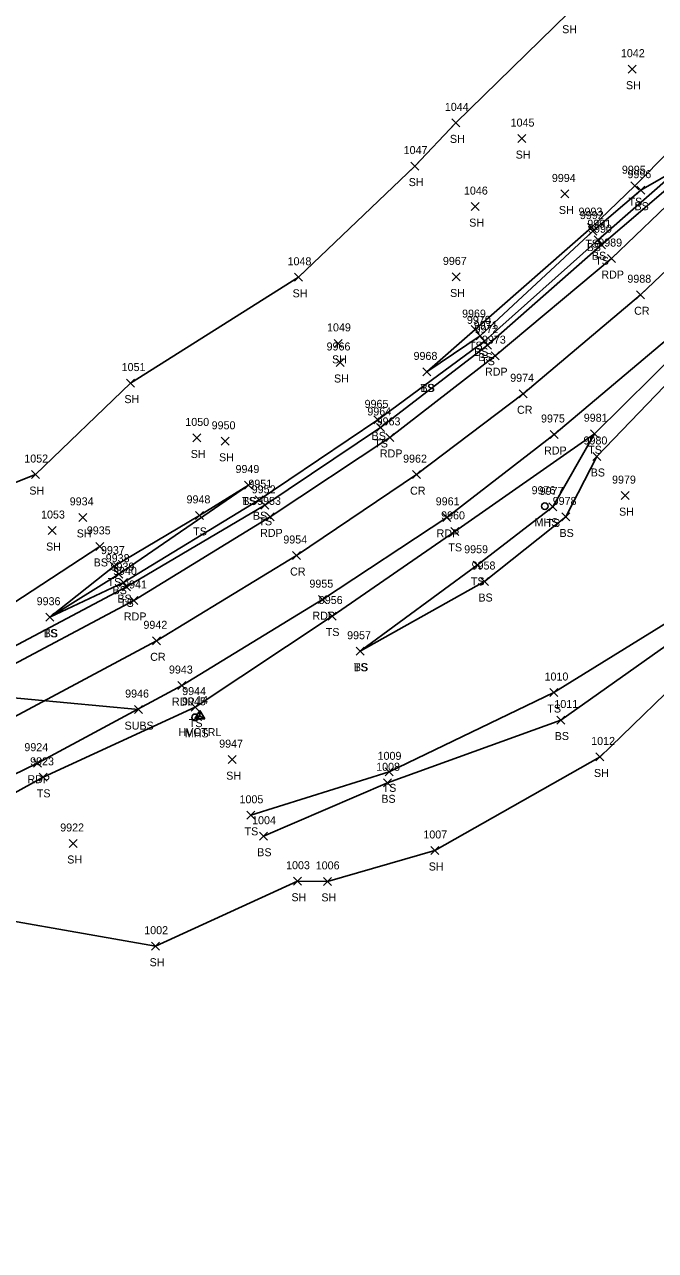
# Model space of a CAD drawing. Extents: x 1651685 to 1653558, y 889533 to 891085.
# Drawn here: x 1652341.8 to 1652499.4, y 889769.1 to 890075.4 of the extents above; entities that cross this region are included whole.
import ezdxf

# ---------------------------------------------------------------- set-up
doc = ezdxf.new("R2010")
doc.units = 0
for name, color, linetype in [('C_A', 7, 'Continuous'), ('C_I', 7, 'Continuous'), ('CPSM', 7, 'Continuous'), ('L_A', 7, 'Continuous'), ('L_I', 7, 'Continuous'), ('L_TIC', 7, 'Continuous'), ('LELB', 7, 'Continuous'), ('LSOGP', 7, 'Continuous'), ('P_A', 7, 'Continuous'), ('P_I', 7, 'Continuous'), ('P_TIC', 7, 'Continuous'), ('PET', 7, 'Continuous'), ('PRC', 7, 'Continuous'), ('U_A', 7, 'Continuous'), ('U_I', 7, 'Continuous'), ('U_TIC', 7, 'Continuous'), ('USA', 7, 'Continuous'), ('USMH', 7, 'Continuous')]:
    doc.layers.add(name, color=color, linetype=linetype)

msp = doc.modelspace()

# ---------------------------------------------------------------- linework, layer by layer
at = {"layer": 'CPSM'}
for p, q in [((1652384.31, 889901.92), (1652385.56, 889904.08)), ((1652386.81, 889901.92), (1652385.56, 889904.08)), ((1652385.56, 889902.64), (1652385.56, 889904.08)), ((1652384.31, 889901.92), (1652385.56, 889902.64)), ((1652384.31, 889901.92), (1652386.81, 889901.92)), ((1652385.56, 889902.64), (1652385.56, 889902.64)), ((1652385.56, 889902.64), (1652386.81, 889901.92))]:
    msp.add_line(p, q, dxfattribs=at)
at = {"layer": 'L_TIC'}
for points in [[(1652492.54, 890063.25), (1652494.54, 890065.25)], [(1652494.54, 890063.25), (1652492.54, 890065.25)], [(1652448.56, 890049.84), (1652450.56, 890051.84)], [(1652450.56, 890049.84), (1652448.56, 890051.84)], [(1652464.99, 890045.91), (1652466.99, 890047.91)], [(1652466.99, 890045.91), (1652464.99, 890047.91)], [(1652438.27, 890039.04), (1652440.27, 890041.04)], [(1652440.27, 890039.04), (1652438.27, 890041.04)], [(1652493.27, 890034.14), (1652495.27, 890036.14)], [(1652495.27, 890034.14), (1652493.27, 890036.14)], [(1652475.78, 890032.08), (1652477.78, 890034.08)], [(1652477.78, 890032.08), (1652475.78, 890034.08)], [(1652494.71, 890033.02), (1652496.71, 890035.02)], [(1652496.71, 890033.02), (1652494.71, 890035.02)], [(1652453.38, 890028.92), (1652455.38, 890030.92)], [(1652455.38, 890028.92), (1652453.38, 890030.92)], [(1652482.45, 890023.67), (1652484.45, 890025.67)], [(1652484.45, 890023.67), (1652482.45, 890025.67)], [(1652482.78, 890022.8), (1652484.78, 890024.8)], [(1652484.78, 890022.8), (1652482.78, 890024.8)], [(1652484.07, 890020.64), (1652486.07, 890022.64)], [(1652486.07, 890020.64), (1652484.07, 890022.64)], [(1652484.92, 890019.39), (1652486.92, 890021.39)], [(1652486.92, 890019.39), (1652484.92, 890021.39)], [(1652409.27, 890011.26), (1652411.27, 890013.26)], [(1652411.27, 890011.26), (1652409.27, 890013.26)], [(1652448.61, 890011.35), (1652450.61, 890013.35)], [(1652450.61, 890011.35), (1652448.61, 890013.35)], [(1652453.4, 889998.19), (1652455.4, 890000.19)], [(1652455.4, 889998.19), (1652453.4, 890000.19)], [(1652419.14, 889994.75), (1652421.14, 889996.75)], [(1652421.14, 889994.75), (1652419.14, 889996.75)], [(1652454.64, 889996.63), (1652456.64, 889998.63)], [(1652456.64, 889996.63), (1652454.64, 889998.63)], [(1652455.7, 889995.32), (1652457.7, 889997.32)], [(1652457.7, 889995.32), (1652455.7, 889997.32)], [(1652456.46, 889994.31), (1652458.46, 889996.31)], [(1652458.46, 889994.31), (1652456.46, 889996.31)], [(1652419.61, 889989.98), (1652421.61, 889991.98)], [(1652421.61, 889989.98), (1652419.61, 889991.98)], [(1652367.26, 889984.83), (1652369.26, 889986.83)], [(1652369.26, 889984.83), (1652367.26, 889986.83)], [(1652441.28, 889987.62), (1652443.28, 889989.62)], [(1652443.28, 889987.62), (1652441.28, 889989.62)], [(1652441.28, 889987.62), (1652443.28, 889989.62)], [(1652443.28, 889987.62), (1652441.28, 889989.62)], [(1652429.05, 889975.64), (1652431.05, 889977.64)], [(1652431.05, 889975.64), (1652429.05, 889977.64)], [(1652429.74, 889973.75), (1652431.74, 889975.75)], [(1652431.74, 889973.75), (1652429.74, 889975.75)], [(1652383.82, 889971.13), (1652385.82, 889973.13)], [(1652385.82, 889971.13), (1652383.82, 889973.13)], [(1652390.89, 889970.29), (1652392.89, 889972.29)], [(1652392.89, 889970.29), (1652390.89, 889972.29)], [(1652483.18, 889972.18), (1652485.18, 889974.18)], [(1652485.18, 889972.18), (1652483.18, 889974.18)], [(1652483.18, 889972.18), (1652485.18, 889974.18)], [(1652485.18, 889972.18), (1652483.18, 889974.18)], [(1652483.78, 889966.5), (1652485.78, 889968.5)], [(1652485.78, 889966.5), (1652483.78, 889968.5)], [(1652343.51, 889961.98), (1652345.51, 889963.98)], [(1652345.51, 889961.98), (1652343.51, 889963.98)], [(1652396.76, 889959.36), (1652398.76, 889961.36)], [(1652398.76, 889959.36), (1652396.76, 889961.36)], [(1652396.76, 889959.36), (1652398.76, 889961.36)], [(1652398.76, 889959.36), (1652396.76, 889961.36)], [(1652399.4, 889955.7), (1652401.4, 889957.7)], [(1652401.4, 889955.7), (1652399.4, 889957.7)], [(1652400.81, 889954.3), (1652402.81, 889956.3)], [(1652402.81, 889954.3), (1652400.81, 889956.3)], [(1652490.82, 889956.72), (1652492.82, 889958.72)], [(1652492.82, 889956.72), (1652490.82, 889958.72)], [(1652355.35, 889951.28), (1652357.35, 889953.28)], [(1652357.35, 889951.28), (1652355.35, 889953.28)], [(1652384.53, 889951.78), (1652386.53, 889953.78)], [(1652386.53, 889951.78), (1652384.53, 889953.78)], [(1652472.73, 889953.89), (1652474.73, 889955.89)], [(1652474.73, 889953.89), (1652472.73, 889955.89)], [(1652475.98, 889951.39), (1652477.98, 889953.39)], [(1652477.98, 889951.39), (1652475.98, 889953.39)], [(1652347.7, 889947.99), (1652349.7, 889949.99)], [(1652349.7, 889947.99), (1652347.7, 889949.99)], [(1652448.26, 889947.79), (1652450.26, 889949.79)], [(1652450.26, 889947.79), (1652448.26, 889949.79)], [(1652359.62, 889944.03), (1652361.62, 889946.03)], [(1652361.62, 889944.03), (1652359.62, 889946.03)], [(1652363.15, 889939.11), (1652365.15, 889941.11)], [(1652365.15, 889939.11), (1652363.15, 889941.11)], [(1652453.88, 889939.32), (1652455.88, 889941.32)], [(1652455.88, 889939.32), (1652453.88, 889941.32)], [(1652364.34, 889937.1), (1652366.34, 889939.1)], [(1652366.34, 889937.1), (1652364.34, 889939.1)], [(1652365.56, 889934.99), (1652367.56, 889936.99)], [(1652367.56, 889934.99), (1652365.56, 889936.99)], [(1652366.25, 889933.93), (1652368.25, 889935.93)], [(1652368.25, 889933.93), (1652366.25, 889935.93)], [(1652455.73, 889935.26), (1652457.73, 889937.26)], [(1652457.73, 889935.26), (1652455.73, 889937.26)], [(1652417.63, 889926.64), (1652419.63, 889928.64)], [(1652419.63, 889926.64), (1652417.63, 889928.64)], [(1652347.15, 889926.34), (1652349.15, 889928.34)], [(1652349.15, 889926.34), (1652347.15, 889928.34)], [(1652347.15, 889926.34), (1652349.15, 889928.34)], [(1652349.15, 889926.34), (1652347.15, 889928.34)], [(1652347.15, 889926.34), (1652349.15, 889928.34)], [(1652349.15, 889926.34), (1652347.15, 889928.34)], [(1652424.64, 889917.85), (1652426.64, 889919.85)], [(1652426.64, 889917.85), (1652424.64, 889919.85)], [(1652424.64, 889917.85), (1652426.64, 889919.85)], [(1652426.64, 889917.85), (1652424.64, 889919.85)], [(1652472.98, 889907.53), (1652474.98, 889909.53)], [(1652474.98, 889907.53), (1652472.98, 889909.53)], [(1652383.44, 889903.89), (1652385.44, 889905.89)], [(1652385.44, 889903.89), (1652383.44, 889905.89)], [(1652474.79, 889900.66), (1652476.79, 889902.66)], [(1652476.79, 889900.66), (1652474.79, 889902.66)], [(1652392.68, 889890.76), (1652394.68, 889892.76)], [(1652394.68, 889890.76), (1652392.68, 889892.76)], [(1652484.54, 889891.44), (1652486.54, 889893.44)], [(1652486.54, 889891.44), (1652484.54, 889893.44)], [(1652431.84, 889887.72), (1652433.84, 889889.72)], [(1652433.84, 889887.72), (1652431.84, 889889.72)], [(1652345.46, 889886.35), (1652347.46, 889888.35)], [(1652347.46, 889886.35), (1652345.46, 889888.35)], [(1652431.48, 889884.98), (1652433.48, 889886.98)], [(1652433.48, 889884.98), (1652431.48, 889886.98)], [(1652397.35, 889876.86), (1652399.35, 889878.86)], [(1652399.35, 889876.86), (1652397.35, 889878.86)], [(1652400.49, 889871.63), (1652402.49, 889873.63)], [(1652402.49, 889871.63), (1652400.49, 889873.63)], [(1652352.97, 889869.82), (1652354.97, 889871.82)], [(1652354.97, 889869.82), (1652352.97, 889871.82)], [(1652443.27, 889868.07), (1652445.27, 889870.07)], [(1652445.27, 889868.07), (1652443.27, 889870.07)], [(1652408.98, 889860.39), (1652410.98, 889862.39)], [(1652410.98, 889860.39), (1652408.98, 889862.39)], [(1652416.45, 889860.35), (1652418.45, 889862.35)], [(1652418.45, 889860.35), (1652416.45, 889862.35)], [(1652373.55, 889844.16), (1652375.55, 889846.16)], [(1652375.55, 889844.16), (1652373.55, 889846.16)]]:
    msp.add_lwpolyline(points, dxfattribs=at)
at = {"layer": 'LELB'}
for points in [[(1652293.22, 889915.66), (1652303.09, 889907.93), (1652317.35, 889908.79), (1652320.69, 889910.3), (1652331.92, 889916.22), (1652367.25, 889934.93), (1652401.81, 889955.3), (1652430.74, 889974.75), (1652457.46, 889995.31), (1652485.92, 890020.39), (1652507.16, 890038.54), (1652516.29, 890046.9), (1652543.45, 890076.69), (1652569.75, 890105.32), (1652598.99, 890142.55), (1652623.84, 890175.33), (1652642.78, 890202.62), (1652649.43, 890213.08), (1652650.34, 890219.8), (1652662.3, 890235.67), (1652673.05, 890250.91), (1652676.63, 890257.99), (1652674.28, 890264.42)], [(1652348.15, 889927.34), (1652366.56, 889935.99), (1652400.4, 889956.7), (1652430.05, 889976.64), (1652456.7, 889996.32), (1652485.07, 890021.64), (1652505.87, 890039.82), (1652515.19, 890048.17), (1652541.97, 890077.83), (1652568.76, 890106.07), (1652597.37, 890144.26), (1652620.77, 890177.54), (1652638.78, 890206.49), (1652647.21, 890219), (1652658.7, 890237.83), (1652668.92, 890254.32), (1652671.69, 890259.27)], [(1652059.96, 889769.15), (1652077.1, 889776.34), (1652118.69, 889793.55), (1652148.83, 889805.14), (1652195.57, 889824.7), (1652235.22, 889839.02), (1652273.17, 889851.71), (1652312.19, 889868.5), (1652346.46, 889887.35), (1652384.44, 889904.89), (1652418.63, 889927.64), (1652449.26, 889948.79), (1652484.18, 889973.18), (1652505.9, 889994.66), (1652536.9, 890025.51), (1652566.28, 890055.69), (1652594.63, 890083.58), (1652622.18, 890122.04), (1652650.06, 890154.47), (1652669.87, 890181.83), (1652676.09, 890189.41), (1652687.77, 890202.23), (1652700.09, 890224.17)], [(1652442.28, 889988.62), (1652454.4, 889999.19), (1652483.45, 890024.67), (1652494.27, 890035.14), (1652511.88, 890052.95), (1652537.3, 890082.09), (1652561.99, 890110.81), (1652590.74, 890149.47), (1652610.85, 890183.15), (1652631.18, 890211.95), (1652637.71, 890221.97)], [(1652425.64, 889918.85), (1652456.73, 889936.26), (1652476.98, 889952.39), (1652484.78, 889967.5), (1652507.93, 889991.53), (1652539.73, 890022.77), (1652568.75, 890053.15), (1652596.44, 890082.38), (1652624.72, 890120.12), (1652650.78, 890153.9), (1652671.99, 890180.33), (1652678.44, 890186.86), (1652688.88, 890200.58)], [(1652442.28, 889988.62), (1652455.64, 889997.63), (1652483.78, 890023.8), (1652495.71, 890034.02), (1652505.87, 890039.82)], [(1652425.64, 889918.85), (1652454.88, 889940.32), (1652473.73, 889954.89), (1652484.18, 889973.18)], [(1652398.35, 889877.86), (1652432.84, 889888.72), (1652473.98, 889908.53), (1652503.63, 889926.84), (1652527.76, 889943.52), (1652552.29, 889965.96)], [(1652348.15, 889927.34), (1652364.15, 889940.11), (1652385.53, 889952.78), (1652397.76, 889960.36)], [(1652348.15, 889927.34), (1652365.34, 889938.1), (1652397.76, 889960.36)], [(1652401.49, 889872.63), (1652432.48, 889885.98), (1652475.79, 889901.66), (1652505.98, 889923.02), (1652542.27, 889949.72)], [(1652298.96, 889913.59), (1652303.02, 889910.85), (1652329.14, 889924.47), (1652360.62, 889945.03)]]:
    msp.add_lwpolyline(points, dxfattribs=at)
at = {"layer": 'LSOGP'}
for points in [[(1652318.58, 889855.03), (1652374.55, 889845.16), (1652409.98, 889861.38), (1652417.45, 889861.35), (1652444.27, 889869.07), (1652485.55, 889892.44), (1652509.97, 889916.1), (1652542.26, 889949.72), (1652552.29, 889965.95), (1652571.67, 889995.46), (1652586.67, 890018.83), (1652616.64, 890057.03), (1652642.24, 890083.82)], [(1652477.61, 890078.23), (1652449.56, 890050.84), (1652439.27, 890040.04), (1652410.27, 890012.27), (1652368.26, 889985.83), (1652344.51, 889962.98), (1652311.88, 889950.06)]]:
    msp.add_lwpolyline(points, dxfattribs=at)
at = {"layer": 'P_TIC'}
for points in [[(1652487.38, 890015.94), (1652489.38, 890017.94)], [(1652489.38, 890015.94), (1652487.38, 890017.94)], [(1652494.64, 890006.9), (1652496.64, 890008.9)], [(1652496.64, 890006.9), (1652494.64, 890008.9)], [(1652458.32, 889991.68), (1652460.32, 889993.68)], [(1652460.32, 889991.68), (1652458.32, 889993.68)], [(1652465.37, 889982.16), (1652467.37, 889984.16)], [(1652467.37, 889982.16), (1652465.37, 889984.16)], [(1652432.06, 889971.26), (1652434.06, 889973.26)], [(1652434.06, 889971.26), (1652432.06, 889973.26)], [(1652473.07, 889971.99), (1652475.07, 889973.99)], [(1652475.07, 889971.99), (1652473.07, 889973.99)], [(1652438.67, 889961.96), (1652440.67, 889963.96)], [(1652440.67, 889961.96), (1652438.67, 889963.96)], [(1652402.15, 889951.41), (1652404.15, 889953.41)], [(1652404.15, 889951.41), (1652402.15, 889953.41)], [(1652446.25, 889951.29), (1652448.25, 889953.29)], [(1652448.25, 889951.29), (1652446.25, 889953.29)], [(1652408.7, 889941.76), (1652410.7, 889943.76)], [(1652410.7, 889941.76), (1652408.7, 889943.76)], [(1652368.12, 889930.53), (1652370.12, 889932.53)], [(1652370.12, 889930.53), (1652368.12, 889932.53)], [(1652415.22, 889930.73), (1652417.22, 889932.73)], [(1652417.22, 889930.73), (1652415.22, 889932.73)], [(1652373.76, 889920.45), (1652375.76, 889922.45)], [(1652375.76, 889920.45), (1652373.76, 889922.45)], [(1652380.13, 889909.27), (1652382.13, 889911.27)], [(1652382.13, 889909.27), (1652380.13, 889911.27)], [(1652344.02, 889889.88), (1652346.02, 889891.88)], [(1652346.02, 889889.88), (1652344.02, 889891.88)]]:
    msp.add_lwpolyline(points, dxfattribs=at)
at = {"layer": 'PET'}
for points in [[(1652310.07, 889873.86), (1652345.02, 889890.88), (1652381.13, 889910.27), (1652416.22, 889931.73), (1652447.25, 889952.29), (1652474.07, 889972.99), (1652503.7, 889997.94), (1652534.46, 890027.79), (1652563.38, 890057.92), (1652590.11, 890087.92), (1652620.33, 890123.88), (1652646.59, 890156.84), (1652667.23, 890184.01), (1652673.84, 890192.76), (1652698.19, 890224.99), (1652707.05, 890238.8), (1652697.14, 890249.86), (1652688.17, 890260.37)], [(1652333.65, 889912.67), (1652369.12, 889931.53), (1652403.15, 889952.41), (1652433.06, 889972.26), (1652459.32, 889992.68), (1652488.38, 890016.94), (1652517.96, 890045.24), (1652545.96, 890074.03), (1652572.08, 890103.38), (1652602.1, 890139.63), (1652627.16, 890172.83), (1652646.68, 890199.42), (1652655.75, 890211.75), (1652675.09, 890240.6), (1652688.17, 890260.37)]]:
    msp.add_lwpolyline(points, dxfattribs=at)
at = {"layer": 'PRC'}
msp.add_lwpolyline([(1652339.13, 889902.36), (1652374.76, 889921.45), (1652409.7, 889942.76), (1652439.67, 889962.96), (1652466.37, 889983.16), (1652495.64, 890007.9), (1652525.65, 890036.36), (1652554.01, 890065.88), (1652580.92, 890096.26), (1652611.45, 890132.24), (1652636.96, 890165.09), (1652656.96, 890191.59), (1652665.11, 890202.52), (1652686.51, 890233.67), (1652697.14, 890249.86)], dxfattribs=at)
at = {"layer": 'U_TIC'}
for points in [[(1652369.24, 889903.27), (1652371.24, 889905.27)], [(1652371.24, 889903.27), (1652369.24, 889905.27)]]:
    msp.add_lwpolyline(points, dxfattribs=at)
at = {"layer": 'USA'}
msp.add_lwpolyline([(1652325.6, 889908.46), (1652370.24, 889904.27)], dxfattribs=at)
at = {"layer": 'USMH'}
for p, q in [((1652471.78, 889955.07), (1652471.78, 889955.07)), ((1652472.61, 889955.07), (1652472.61, 889955.07)), ((1652384.4, 889902.33), (1652384.4, 889902.33)), ((1652385.23, 889902.33), (1652385.23, 889902.33))]:
    msp.add_line(p, q, dxfattribs=at)
for centre in [(1652471.78, 889955.07), (1652384.4, 889902.33)]:
    msp.add_circle(centre, 0.833, dxfattribs=at)

# ---------------------------------------------------------------- texts
at = {"layer": 'C_A'}
msp.add_text('HVCTRL', height=2, dxfattribs=at).set_placement((1652380.26, 889897.64))
at = {"layer": 'C_I'}
msp.add_text('14', height=2, dxfattribs=at).set_placement((1652384.67, 889905.64))
at = {"layer": 'L_A'}
for s, p in [('SH', (1652476.09, 890073.23)), ('SH', (1652492.02, 890059.25)), ('SH', (1652448.05, 890045.84)), ('SH', (1652464.48, 890041.91)), ('SH', (1652437.76, 890035.04)), ('SH', (1652475.27, 890028.08)), ('TS', (1652492.68, 890030.14)), ('BS', (1652494.15, 890029.02)), ('SH', (1652452.87, 890024.92)), ('TS', (1652481.86, 890019.67)), ('BS', (1652482.22, 890018.8)), ('BS', (1652483.51, 890016.64)), ('TS', (1652484.33, 890015.39)), ('SH', (1652408.76, 890007.26)), ('SH', (1652448.1, 890007.35)), ('TS', (1652452.81, 889994.19)), ('BS', (1652454.08, 889992.63)), ('BS', (1652455.14, 889991.32)), ('SH', (1652418.62, 889990.75)), ('TS', (1652455.87, 889990.31)), ('SH', (1652419.1, 889985.98)), ('TS', (1652440.69, 889983.62)), ('BS', (1652440.72, 889983.62)), ('SH', (1652366.75, 889980.83)), ('BS', (1652428.49, 889971.64)), ('TS', (1652429.15, 889969.75)), ('SH', (1652383.31, 889967.13)), ('SH', (1652390.38, 889966.29)), ('TS', (1652482.59, 889968.18)), ('TS', (1652482.59, 889968.18)), ('BS', (1652483.22, 889962.5)), ('SH', (1652343, 889957.98)), ('TS', (1652396.17, 889955.36)), ('BS', (1652396.21, 889955.36)), ('BS', (1652398.84, 889951.7)), ('SH', (1652490.3, 889952.72)), ('TS', (1652400.22, 889950.3)), ('TS', (1652472.14, 889949.89)), ('SH', (1652354.83, 889947.28)), ('TS', (1652383.93, 889947.78)), ('BS', (1652475.42, 889947.39)), ('SH', (1652347.19, 889943.99)), ('TS', (1652447.67, 889943.79)), ('BS', (1652359.06, 889940.03)), ('TS', (1652362.56, 889935.11)), ('BS', (1652363.78, 889933.1)), ('TS', (1652453.29, 889935.32)), ('BS', (1652365, 889930.99)), ('TS', (1652365.66, 889929.93)), ('BS', (1652455.17, 889931.26)), ('TS', (1652346.56, 889922.34)), ('BS', (1652346.59, 889922.34)), ('BS', (1652346.59, 889922.34)), ('TS', (1652417.04, 889922.64)), ('TS', (1652424.05, 889913.85)), ('BS', (1652424.08, 889913.85)), ('TS', (1652472.39, 889903.53)), ('TS', (1652382.85, 889899.89)), ('BS', (1652474.23, 889896.66)), ('SH', (1652392.17, 889886.76)), ('SH', (1652484.03, 889887.44)), ('TS', (1652431.25, 889883.72)), ('TS', (1652344.87, 889882.35)), ('BS', (1652430.92, 889880.98)), ('TS', (1652396.76, 889872.86)), ('SH', (1652352.46, 889865.82)), ('BS', (1652399.93, 889867.63)), ('SH', (1652442.76, 889864.07)), ('SH', (1652408.47, 889856.39)), ('SH', (1652415.94, 889856.35)), ('SH', (1652373.04, 889840.16))]:
    msp.add_text(s, height=2, dxfattribs=at).set_placement(p)
at = {"layer": 'L_I'}
for s, p in [('1042', (1652490.76, 890067.25)), ('1044', (1652446.79, 890053.84)), ('1045', (1652463.22, 890049.91)), ('1047', (1652436.5, 890043.04)), ('9995', (1652491.01, 890038.14)), ('9996', (1652492.4, 890037.02)), ('9994', (1652473.52, 890036.08)), ('1046', (1652451.56, 890032.92)), ('9993', (1652480.19, 890027.67)), ('9992', (1652480.52, 890026.8)), ('9991', (1652482.38, 890024.64)), ('9990', (1652482.57, 890023.39)), ('1048', (1652407.5, 890015.26)), ('9967', (1652446.3, 890015.35)), ('9969', (1652451.09, 890002.19)), ('9970', (1652452.3, 890000.63)), ('1049', (1652417.36, 889998.75)), ('9971', (1652454.01, 889999.32)), ('9972', (1652454.2, 889998.31)), ('9966', (1652417.25, 889993.98)), ('9968', (1652438.97, 889991.62)), ('9968', (1652438.97, 889991.62)), ('1051', (1652366.06, 889988.83)), ('9965', (1652426.74, 889979.64)), ('9964', (1652427.43, 889977.75)), ('9981', (1652481.49, 889976.18)), ('9981', (1652481.49, 889976.18)), ('1050', (1652381.96, 889975.13)), ('9950', (1652388.54, 889974.29)), ('9980', (1652481.43, 889970.5)), ('1052', (1652341.74, 889965.98)), ('9949', (1652394.5, 889963.36)), ('9949', (1652394.5, 889963.36)), ('9979', (1652488.55, 889960.72)), ('9951', (1652397.71, 889959.7)), ('9952', (1652398.55, 889958.3)), ('9977', (1652470.47, 889957.89)), ('9934', (1652353.09, 889955.28)), ('9948', (1652382.27, 889955.78)), ('9978', (1652473.72, 889955.39)), ('1053', (1652345.93, 889951.99)), ('9960', (1652445.86, 889951.79)), ('9935', (1652357.36, 889948.03)), ('9937', (1652360.89, 889943.11)), ('9959', (1652451.62, 889943.32)), ('9938', (1652362.08, 889941.1)), ('9939', (1652363.29, 889938.99)), ('9958', (1652453.47, 889939.26)), ('9940', (1652363.9, 889937.93)), ('9936', (1652344.83, 889930.34)), ('9936', (1652344.83, 889930.34)), ('9936', (1652344.83, 889930.34)), ('9956', (1652415.31, 889930.64)), ('9957', (1652422.38, 889921.85)), ('9957', (1652422.38, 889921.85)), ('1010', (1652471.69, 889911.53)), ('9944', (1652381.18, 889907.89)), ('1011', (1652474.15, 889904.66)), ('9947', (1652390.42, 889894.76)), ('1012', (1652483.34, 889895.44)), ('9923', (1652343.2, 889890.35)), ('1009', (1652429.99, 889891.72)), ('1008', (1652429.63, 889888.98)), ('1005', (1652395.5, 889880.86)), ('1004', (1652398.64, 889875.63)), ('9922', (1652350.71, 889873.82)), ('1007', (1652441.42, 889872.07)), ('1003', (1652407.13, 889864.39)), ('1006', (1652414.54, 889864.35)), ('1002', (1652371.7, 889848.16))]:
    msp.add_text(s, height=2, dxfattribs=at).set_placement(p)
at = {"layer": 'P_A'}
for s, p in [('RDP', (1652485.87, 890011.94)), ('CR', (1652494.07, 890002.9)), ('RDP', (1652456.81, 889987.68)), ('CR', (1652464.81, 889978.16)), ('RDP', (1652430.55, 889967.26)), ('RDP', (1652471.56, 889967.99)), ('CR', (1652438.1, 889957.96)), ('RDP', (1652400.64, 889947.41)), ('RDP', (1652444.73, 889947.29)), ('CR', (1652408.13, 889937.76)), ('RDP', (1652366.61, 889926.53)), ('RDP', (1652413.71, 889926.73)), ('CR', (1652373.19, 889916.45)), ('RDP', (1652378.62, 889905.27)), ('RDP', (1652342.51, 889885.88))]:
    msp.add_text(s, height=2, dxfattribs=at).set_placement(p)
at = {"layer": 'P_I'}
for s, p in [('9989', (1652485.11, 890019.94)), ('9988', (1652492.38, 890010.9)), ('9973', (1652456.06, 889995.68)), ('9974', (1652463.11, 889986.16)), ('9975', (1652470.81, 889975.99)), ('9963', (1652429.75, 889975.26)), ('9962', (1652436.36, 889965.96)), ('9953', (1652399.89, 889955.41)), ('9961', (1652444.51, 889955.29)), ('9954', (1652406.44, 889945.76)), ('9941', (1652366.43, 889934.53)), ('9955', (1652412.96, 889934.73)), ('9942', (1652371.5, 889924.45)), ('9943', (1652377.87, 889913.27)), ('9924', (1652341.76, 889893.88))]:
    msp.add_text(s, height=2, dxfattribs=at).set_placement(p)
at = {"layer": 'U_A'}
for s, p in [('MHS', (1652469.2, 889950.07)), ('SUBS', (1652366.78, 889899.27)), ('MHS', (1652381.82, 889897.33))]:
    msp.add_text(s, height=2, dxfattribs=at).set_placement(p)
at = {"layer": 'U_I'}
for s, p in [('9976', (1652468.46, 889958.07)), ('9946', (1652366.93, 889907.27)), ('9945', (1652381.14, 889905.33))]:
    msp.add_text(s, height=2, dxfattribs=at).set_placement(p)

doc.saveas('drawing.dxf')
